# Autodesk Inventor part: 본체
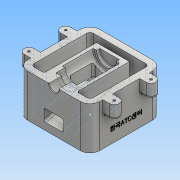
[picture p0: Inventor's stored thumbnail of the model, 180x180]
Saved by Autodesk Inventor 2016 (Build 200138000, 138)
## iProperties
Created: 2018-01
Part Number: 본체
Material: 알루미늄 6061
Document SubType Name: Modeling
Designer: Administrator
Density: 2.7 g/cm^3
Appearance: 알루미늄 - 평지
Mass: 994.844 g
Surface Area: 837.492 cm^2
Volume: 368.461 cm^3
Author: Administrator
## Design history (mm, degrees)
sketch "스케치1"
  geometry: L1 (-40, -55)-(40, -55); L2 (55, -40)-(55, 40); L3 (40, 55)-(-40, 55); L4 (-55, 40)-(-55, -40); L5 (-55, -55)-(55, 55); L6 (55, -55)-(-55, 55); A1 r 15 centre (-40, 40) between (-40, 55) and (-55, 40); A2 r 15 centre (40, 40) between (55, 40) and (40, 55); A3 r 15 centre (40, -40) between (40, -55) and (55, -40); A4 r 15 centre (-40, -40) between (-55, -40) and (-40, -55); 1 further point
  constraints: 12 end point, 8 point on circle, 8 point on line, 8 tangent, 4 centre point, 3 equal radius, 2 midpoint, 2 parallel, 1 horizontal, 1 perpendicular
  dimensions: "d0" = 110 distance of L6.end L5.end; "d1" = 110 distance of L5.end L6.start; "d2" = 15 radius of A1
extrude "돌출1" new body sketch "스케치1" distance "d3" = 65; taper "d4" = 0 deg
sketch "스케치2"
  geometry: L1 (40, 55)-(-40, 55) reference; L2 (55, -40)-(55, 40) reference; L3 (40.78, 35.5)-(65, 35.5); L4 (65, 35.5)-(65, 20.5); L5 (65, 20.5)-(40.78, 20.5); L6 (40.78, 20.5)-(40.78, 35.5); A1 r 7.5 centre (65, 28) between (65, 20.5) and (65, 35.5); 1 further point
  constraints: 8 end point, 2 parallel, 2 point on circle, 1 centre point, 1 horizontal, 1 midpoint, 1 perpendicular
  dimensions: "d5" = 27 distance from line of L1 A1.centre; "d6" = 10 distance between parallel lines of L2 L4; "d7" = 7.5 radius of A1
extrude "돌출2" join sketch "스케치2" distance "d8" = 20; taper "d9" = 0 deg
feature "쉘1" dims "d13" = 10
sketch "스케치3"
  geometry: L1 (-40, 45)-(40, 45); L2 (45, 40)-(45, -40); L3 (40, -45)-(-40, -45); L4 (-45, -40)-(-45, 40); A1 r 15 centre (-40, 40) between (-40, 55) and (-55, 40) reference; A2 r 15 centre (-40, -40) between (-55, -40) and (-40, -55) reference; A3 r 15 centre (40, -40) between (40, -55) and (55, -40) reference; A4 r 15 centre (40, 40) between (55, 40) and (40, 55) reference; A5 r 5 centre (40, 40) between (45, 40) and (40, 45); A6 r 5 centre (40, -40) between (40, -45) and (45, -40); A7 r 5 centre (-40, -40) between (-45, -40) and (-40, -45); A8 r 5 centre (-40, 40) between (-40, 45) and (-45, 40); 1 further point
  constraints: 8 end point, 8 point on circle, 4 centre point
extrude "돌출3" cut sketch "스케치3" stored distance "d14" = 20; taper "d15" = 0 deg
sketch "스케치4"
  geometry: L1 (-45, 0)-(-45, 65) reference; L2 (-45, 8.564)-(35, 30); L3 (35, 30)-(35, 65); L4 (-40, 65)-(40, 65) reference; L5 (55, 0)-(55, 65) reference; L6 (40, 0)-(-40, 0) reference; L7 (-45, 65)-(35, 65); L8 (40, 65)-(-40, 65) reference; 1 further point
  constraints: 6 end point, 2 point on line, 1 collinear, 1 vertical
  dimensions: "d16" = 20 distance between parallel lines of L5 L3; "d17" = 30 distance from line of L6 L2.end; "d18" = 105 deg angle of L2 L1
extrude "돌출4" join sketch "스케치4" stored distance "d19" = 50; taper "d20" = 0 deg
sketch "스케치5"
  geometry: L1 (-40, 65)-(-55, 65) reference; L2 (55, 0)-(55, 65) reference; L3 (-55, 65)-(55, 65); L4 (-55, 0)-(-55, 65) reference; L5 (-55, 57.5)-(-36, 57.5); L6 (-36, 57.5)-(-36, 49); L7 (-36, 49)-(-22, 49); L8 (-22, 49)-(-22, 45); L9 (-22, 45)-(25, 45); L10 (25, 45)-(25, 50); L11 (25, 50)-(30, 50); L12 (20.5, 45)-(35.5, 45) reference; L13 (30, 50)-(30, 65); 1 further point
  constraints: 18 end point, 6 perpendicular, 2 horizontal, 2 point on line, 1 parallel
  dimensions: "d21" = 15 diameter of L5 L3; "d22" = 32 diameter of L7 L3; "d23" = 40 diameter of L9 L3; "d24" = 30 diameter of L11 L3; "d25" = 19 distance between parallel lines of L4 L6; "d26" = 14 distance between parallel lines of L6 L8; "d27" = 47 distance between parallel lines of L10 L8; "d28" = 5 distance between parallel lines of L13 L10
revolve "회전1" sketch "스케치5" stored, may be unused: angle "d29" = 90 deg
sketch "스케치10"
  geometry: 1 further point
sketch "스케치12"
  geometry: L1 (-55, 0)-(-55, 65) reference; L2 (-55, 11.061)-(20, 31.157); L3 (35, 30)-(-45, 8.564) reference; L4 (-55, 29.061)-(-17, 39.243); L5 (-55, 29.061)-(-55, 11.061); L6 (40, 0)-(-40, 0) reference; L7 (-22, 49)-(-22, 65) reference; L8 (25, 50)-(25, 65) reference; L9 (-17, 39.243)-(20, 31.157); 1 further point
  constraints: 8 end point, 2 point on line, 1 parallel, 1 vertical
  dimensions: "d52" = 5 distance between parallel lines of L3 L2; "d53" = 75 deg angle of L1 L4; "d54" = 18 distance of L2.start L4.start; "d59" = 5 distance from line of L7 L4.end; "d60" = 5 distance from line of L2.end L8
extrude "돌출8" cut sketch "스케치12" stored distance "d55" = 30; taper "d56" = 0 deg
sketch "스케치13"
  geometry: L1 (15, 25)-(20, 25) reference; L2 (-15, 20)-(15, 20); L3 (15, 20)-(15, -17); L4 (15, -17)-(-15, -17); L5 (-15, -17)-(-15, 20); L6 (-15, 20)-(15, -17); L7 (15, 20)-(-15, -17); 3 further points
  constraints: 12 end point, 3 midpoint, 2 parallel, 1 horizontal, 1 perpendicular, 1 vertical alignment
  dimensions: "d61" = 30 distance of L3.end L4.end; "d62" = 37 distance of L2.end L3.end; "d63" = 5 distance between parallel lines of L2 L1
extrude "돌출9" cut sketch "스케치13" stored distance "d64" = 30; taper "d65" = 0 deg
hole "구멍1" diameter "d68" = 3.242; stored, may be unused: countersink angle "d72" = 90 deg, drill point angle "d74" = 118 deg; dims "d66" = 10, "d67" = 10, "d69" = 9, "d70" = 4, "d71" = 2, "d73" = 11
fillet "모깎기2" dims "d82" = 1
fillet "모깎기3" dims "d83" = 3
fillet "모깎기4" dims "d84" = 3
fillet "모깎기5" dims "d85" = 3
fillet "모깎기6" dims "d86" = 3
fillet "모깎기7" dims "d87" = 3
chamfer "모따기1" distance "d88" = 1; stored, may be unused: second distance "d89" = 2, angle "d90" = 45 deg
sketch "스케치15"
  geometry: L1 (0, 80)-(0, 0) reference; L2 (0, -15)-(-65, -15) reference; 2 further points
  constraints: 1 other
  dimensions: "d91" = 55 distance from line of L2 point (-20, 40); "d92" = 20 distance from line of L1 point (-20, 40)
feature "엠보싱1" sketch "스케치15" dims "d0" = 110, "d1" = 110, "d2" = 15, "d93" = 0.5, "d94" = 0
node "솔리드1"
pattern_linear "직사각형 패턴1" dims "d12" = 56
mirror "대칭1"
pattern_linear "직사각형 패턴2" dims "d77" = 56
